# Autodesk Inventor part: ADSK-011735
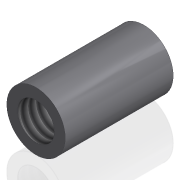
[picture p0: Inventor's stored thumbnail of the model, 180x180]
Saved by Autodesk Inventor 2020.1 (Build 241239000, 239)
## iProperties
Created: 1999-11
Part Number: ADSK-011735
Material: Acier doux
Description: HELICOIL,#10-32NFX0.380
Document SubType Name: Modeling
Designer: lnowak
Density: 7.86 g/cm^3
Appearance: Metal-Steel(Polish)
Mass: 0.9468 g
Surface Area: 2.76674 cm^2
Volume: 0.120458 cm^3
Control State: 0
Checked Out: False
Last Check In By: lnowak
Master: False
Shininess: 0.0
Length Units: 11269
Angle Units: 11279
Time Units: 11290
Mass Units: 11283
Length Display Precision: 3
Angle Display Precision: 2
Compacted: True
Material Desc: HELICOIL, #10-32NF X 0.38
Material_number: A092958
Dimensions: 5,2x5,2x9,5 mm
Mass: 0,001 kg
DocNumber: ADSK-011735.ipt
Folder: 01 - Themengebiete\Simplification\01 - Packaging machine\
VDS_Category: 3D Komponenten
Density: 0.0
Volumn: 0.0
Area: 0.0
PropertySet Name: Model Information
Author: lnowak
Revision Number: -
Title: Heli-Coil
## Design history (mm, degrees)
node "Extrusion1" dims "d1" = 9.525, "d2" = 0
node "Hole1" dims "d3" = 3.242, "d4" = 9.525, "d5" = 6.35, "d6" = 60 deg, "d7" = 11.8, "d8" = 118 deg, "d9" = 8
node "Solide1"
node "Corps solides"
node "Corps surfaciques"
sketch "Sketch1"
  geometry: C1 r 2.579 at (0, 0)
  constraints: 1 centre point, 1 other
  dimensions: "d0" = 5.15874 diameter of C1
sketch "Sketch2"
  geometry: C1 r 2.579 at (0, 0) reference; 1 further point
  constraints: 1 coincident
